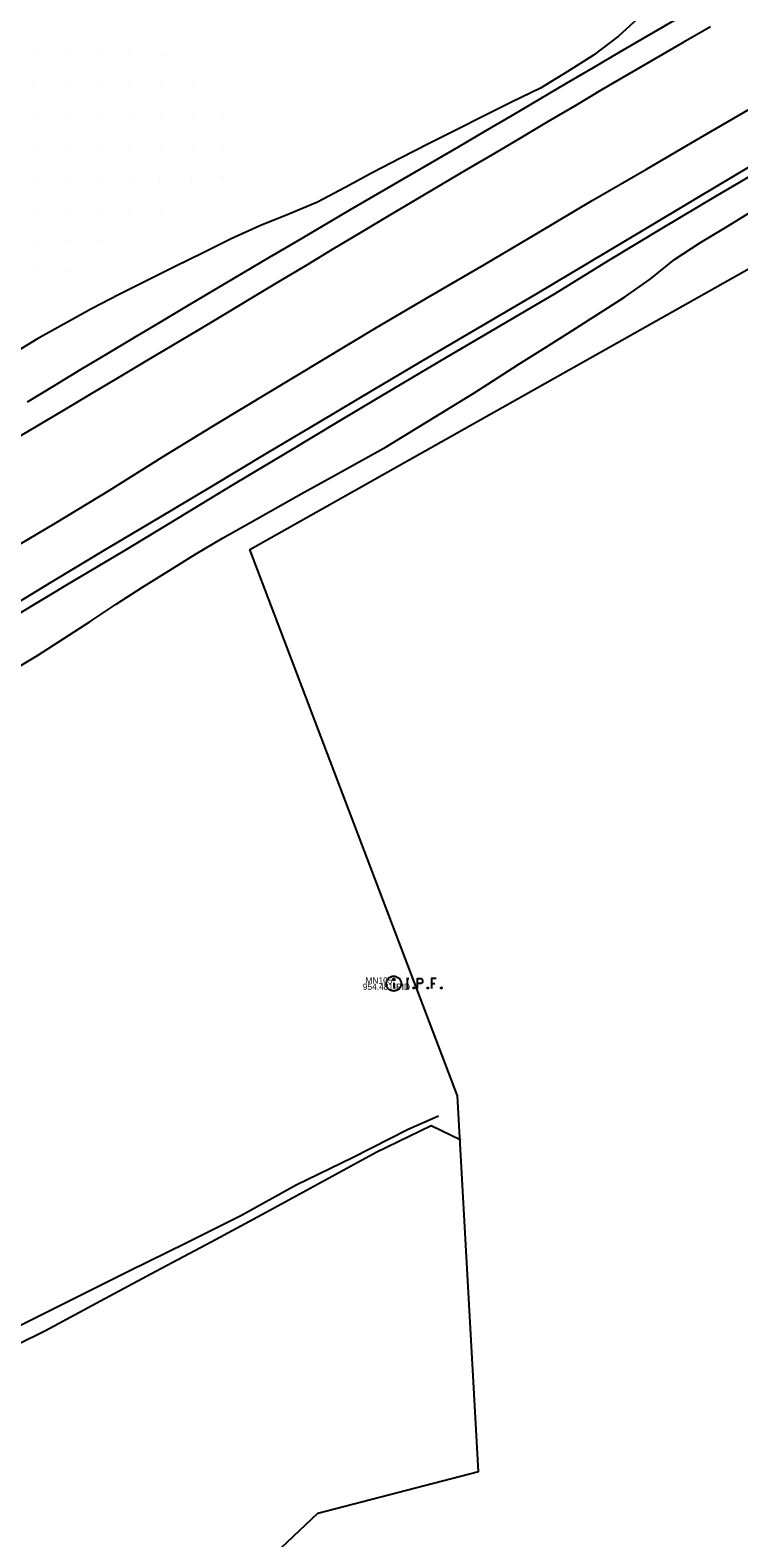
# Model space of a CAD drawing. Extents: x 2262025 to 2264532, y 740981 to 742724.
# Drawn here: x 2263398.7 to 2263511.9, y 741736.1 to 741976.8 of the extents above; entities that cross this region are included whole.
import ezdxf

# ---------------------------------------------------------------- set-up
doc = ezdxf.new("R2010")
doc.units = 0
for name, color, linetype in [('GE_X_Alignment_100_Bearings', 7, 'Continuous'), ('GE_X_Alignment_100_Cardinal_Points', 7, 'Continuous'), ('GE_X_Alignment_100_Curve_Data', 7, 'Continuous'), ('Ground Shots', 7, 'Continuous'), ('HY_X_Spring_Cells', 7, 'Continuous'), ('RS_Raster1', 7, 'Continuous'), ('RW_X_CL', 7, 'Continuous'), ('RW_X_CL_1000_Distances', 7, 'Continuous'), ('RW_X_CL_500_Curve_Data', 7, 'Continuous'), ('SV_X_Control_Cells_Found', 7, 'Continuous'), ('SV_X_Text_Comment', 7, 'Continuous'), ('SV_X_Text_Elevation', 7, 'Continuous')]:
    doc.layers.add(name, color=color, linetype=linetype)

msp = doc.modelspace()

# ---------------------------------------------------------------- linework, layer by layer
at = {"layer": 'GE_X_Alignment_100_Bearings'}
msp.add_lwpolyline([(2263396.73, 741883.54), (2263405.31, 741888.68), (2263413.89, 741893.82), (2263422.45, 741898.99), (2263431.01, 741904.16), (2263439.58, 741909.31), (2263448.16, 741914.45), (2263456.74, 741919.59), (2263465.34, 741924.68), (2263473.97, 741929.74), (2263482.6, 741934.79), (2263491.11, 741940.04), (2263499.67, 741945.22), (2263508.27, 741950.31), (2263516.88, 741955.4)], dxfattribs=at)
at = {"layer": 'GE_X_Alignment_100_Cardinal_Points'}
msp.add_lwpolyline([(2263325.57, 741733.16), (2263334.48, 741737.69), (2263343.4, 741742.23), (2263352.31, 741746.76), (2263361.22, 741751.3), (2263370.13, 741755.83), (2263378.99, 741760.47), (2263387.84, 741765.13), (2263396.69, 741769.79), (2263405.62, 741774.29), (2263414.58, 741778.74), (2263423.53, 741783.19), (2263432.48, 741787.64), (2263441.23, 741792.48), (2263450.22, 741796.85), (2263459.14, 741801.38), (2263463.94, 741803.49)], dxfattribs=at)
at = {"layer": 'GE_X_Alignment_100_Curve_Data'}
for points in [[(2263398.34, 741917.51), (2263402.62, 741920.09), (2263406.9, 741922.68), (2263411.18, 741925.26), (2263415.46, 741927.83), (2263419.75, 741930.39), (2263424.05, 741932.94), (2263428.35, 741935.48), (2263432.66, 741938.02), (2263436.96, 741940.56), (2263441.26, 741943.11), (2263445.57, 741945.64), (2263449.88, 741948.17), (2263454.2, 741950.68), (2263458.52, 741953.18), (2263462.85, 741955.69), (2263467.17, 741958.19), (2263471.48, 741960.73), (2263475.78, 741963.26), (2263480.08, 741965.81), (2263484.38, 741968.36), (2263488.7, 741970.88), (2263493.01, 741973.41), (2263497.33, 741975.92), (2263501.65, 741978.43)], [(2263513.8, 741955.1), (2263505.21, 741949.98), (2263496.62, 741944.85), (2263488.03, 741939.73), (2263479.43, 741934.64), (2263470.8, 741929.57), (2263462.18, 741924.51), (2263453.57, 741919.43), (2263444.98, 741914.3), (2263436.39, 741909.18), (2263427.81, 741904.05), (2263419.22, 741898.93), (2263410.64, 741893.8), (2263402.06, 741888.65), (2263393.5, 741883.49)]]:
    msp.add_lwpolyline(points, dxfattribs=at)
at = {"layer": 'Ground Shots'}
for p, q in [((2263399.7, 741972.96), (2263399.7, 741972.96)), ((2263404.64, 741973.02), (2263404.64, 741973.02)), ((2263409.79, 741973.1), (2263409.79, 741973.1)), ((2263414.61, 741973.12), (2263414.61, 741973.12)), ((2263419.87, 741972.97), (2263419.87, 741972.97)), ((2263399.3, 741967.95), (2263399.3, 741967.95)), ((2263404.6, 741968.07), (2263404.6, 741968.07)), ((2263409.73, 741967.98), (2263409.73, 741967.98)), ((2263414.64, 741967.99), (2263414.64, 741967.99)), ((2263419.75, 741967.96), (2263419.75, 741967.96)), ((2263424.74, 741968.08), (2263424.74, 741968.08)), ((2263399.79, 741963.01), (2263399.79, 741963.01)), ((2263404.68, 741962.95), (2263404.68, 741962.95)), ((2263409.69, 741963.03), (2263409.69, 741963.03)), ((2263414.71, 741963.04), (2263414.71, 741963.04)), ((2263419.71, 741963.3), (2263419.71, 741963.3)), ((2263424.65, 741963.03), (2263424.65, 741963.03)), ((2263429.45, 741962.82), (2263429.45, 741962.82)), ((2263399.56, 741958.03), (2263399.56, 741958.03)), ((2263404.5, 741958.25), (2263404.5, 741958.25)), ((2263409.66, 741958.06), (2263409.66, 741958.06)), ((2263414.67, 741958.06), (2263414.67, 741958.06)), ((2263419.51, 741958.1), (2263419.51, 741958.1)), ((2263424.69, 741957.97), (2263424.69, 741957.97)), ((2263429.66, 741957.98), (2263429.66, 741957.98)), ((2263419.4, 741953.21), (2263419.4, 741953.21)), ((2263424.58, 741953.14), (2263424.58, 741953.14)), ((2263429.68, 741953.28), (2263429.68, 741953.28)), ((2263399.71, 741953.05), (2263399.71, 741953.05)), ((2263404.79, 741953.07), (2263404.79, 741953.07)), ((2263409.69, 741952.95), (2263409.69, 741952.95)), ((2263414.7, 741952.97), (2263414.7, 741952.97)), ((2263399.65, 741947.97), (2263399.65, 741947.97)), ((2263404.68, 741947.98), (2263404.68, 741947.98)), ((2263409.74, 741948.11), (2263409.74, 741948.11)), ((2263414.68, 741948.08), (2263414.68, 741948.08)), ((2263419.69, 741947.93), (2263419.69, 741947.93)), ((2263399.65, 741943.04), (2263399.65, 741943.04)), ((2263404.52, 741943.21), (2263404.52, 741943.21)), ((2263409.66, 741943.08), (2263409.66, 741943.08)), ((2263399.61, 741938.22), (2263399.61, 741938.22)), ((2263404.56, 741938.22), (2263404.56, 741938.22))]:
    msp.add_line(p, q, dxfattribs=at)
at = {"layer": 'RS_Raster1'}
msp.add_lwpolyline([(2262680.86, 741714.81), (2262661.07, 741645.79), (2262765.42, 741624.79), (2262779.22, 741624.19), (2262826.51, 741606.02), (2262832.34, 741584.41), (2262933.09, 741544.98), (2262975.25, 741475.03), (2263024.25, 741455.82), (2263090.74, 741384.5), (2263137.01, 741437.31), (2263272.72, 741623.51), (2263304.66, 741651.89), (2263427.06, 741723.41), (2263444.69, 741740.07), (2263470.34, 741746.73), (2263467.01, 741806.69), (2263433.84, 741893.93), (2263732.51, 742061.95)], dxfattribs=at)
at = {"layer": 'RW_X_CL_1000_Distances'}
for points in [[(2263507.39, 741977.35), (2263503.06, 741974.86), (2263498.72, 741972.37), (2263494.41, 741969.85), (2263490.09, 741967.33), (2263485.8, 741964.77), (2263481.5, 741962.22), (2263477.19, 741959.68), (2263472.88, 741957.15), (2263468.58, 741954.62), (2263464.27, 741952.08), (2263459.98, 741949.52), (2263455.68, 741946.97), (2263451.39, 741944.41), (2263447.1, 741941.85), (2263442.81, 741939.28), (2263438.53, 741936.71), (2263434.24, 741934.13), (2263429.96, 741931.56), (2263425.66, 741929), (2263421.37, 741926.44), (2263417.08, 741923.89), (2263412.78, 741921.33), (2263408.49, 741918.77), (2263404.2, 741916.21), (2263399.91, 741913.65), (2263395.62, 741911.08)], [(2263394.24, 741893.05), (2263402.82, 741898.18), (2263411.38, 741903.33), (2263419.85, 741908.64), (2263428.36, 741913.88), (2263436.94, 741919.01), (2263445.5, 741924.17), (2263454.06, 741929.33), (2263462.68, 741934.39), (2263471.31, 741939.44), (2263479.91, 741944.53), (2263488.52, 741949.61), (2263497.16, 741954.65), (2263505.8, 741959.67), (2263514.44, 741964.69)]]:
    msp.add_lwpolyline(points, dxfattribs=at)
at = {"layer": 'RW_X_CL_500_Curve_Data'}
msp.add_lwpolyline([(2263330.2, 741733.44), (2263339.02, 741738.04), (2263347.88, 741742.61), (2263356.45, 741746.9), (2263365.31, 741751.52), (2263374.29, 741755.93), (2263383.25, 741760.36), (2263392.21, 741764.8), (2263401.18, 741769.23), (2263409.98, 741773.97), (2263418.79, 741778.71), (2263427.63, 741783.39), (2263436.43, 741788.14), (2263445.22, 741792.9), (2263454, 741797.68), (2263462.79, 741801.94), (2263467.51, 741799.66)], dxfattribs=at)
at = {"layer": 'SV_X_Control_Cells_Found'}
for points in [[(2263496.4, 741979.22), (2263492.71, 741975.87), (2263488.72, 741972.85), (2263484.51, 741970.17), (2263480.23, 741967.59), (2263475.75, 741965.38), (2263471.27, 741963.16), (2263466.81, 741960.92), (2263462.35, 741958.67), (2263457.89, 741956.41), (2263453.46, 741954.08), (2263449.07, 741951.71), (2263444.66, 741949.36), (2263440.05, 741947.44), (2263435.42, 741945.58), (2263430.87, 741943.51), (2263426.39, 741941.3), (2263421.91, 741939.09), (2263417.43, 741936.88), (2263412.98, 741934.6), (2263408.54, 741932.31), (2263399.8, 741927.47), (2263395.53, 741924.87)], [(2263391.36, 741871.88), (2263399.93, 741876.97), (2263408.3, 741882.43), (2263412.47, 741885.18), (2263416.67, 741887.89), (2263420.91, 741890.53), (2263425.17, 741893.15), (2263429.45, 741895.71), (2263433.8, 741898.18), (2263442.51, 741903.09), (2263446.89, 741905.48), (2263455.62, 741910.3), (2263469.58, 741918.88), (2263472.59, 741920.8), (2263476.81, 741923.48), (2263481.03, 741926.17), (2263485.24, 741928.85), (2263493.68, 741934.22), (2263497.78, 741937.06), (2263501.63, 741940.21), (2263505.83, 741942.9), (2263510.04, 741945.49), (2263514.35, 741948.12)]]:
    msp.add_lwpolyline(points, dxfattribs=at)
at = {"layer": 'SV_X_Text_Elevation'}
msp.add_line((2263456.81, 741824.73), (2263456.81, 741823.84), dxfattribs=at)
for points in [[(2263458.84, 741825.41), (2263459.2, 741825.41)], [(2263458.84, 741823.81), (2263459.2, 741823.81)], [(2263459.02, 741823.81), (2263459.02, 741825.41)], [(2263459.98, 741824.02), (2263460.03, 741824.02), (2263460.07, 741824), (2263460.1, 741823.95), (2263460.1, 741823.88), (2263460.07, 741823.83), (2263460.03, 741823.81), (2263459.98, 741823.81), (2263459.95, 741823.83), (2263459.91, 741823.88), (2263459.91, 741823.95), (2263459.95, 741824), (2263459.98, 741824.02)], [(2263460.58, 741823.81), (2263460.58, 741825.41), (2263461.11, 741825.41), (2263461.17, 741825.4), (2263461.25, 741825.37), (2263461.28, 741825.35), (2263461.31, 741825.32), (2263461.36, 741825.26), (2263461.39, 741825.19), (2263461.41, 741825.09), (2263461.41, 741824.94), (2263461.4, 741824.89), (2263461.38, 741824.82), (2263461.33, 741824.73), (2263461.29, 741824.69), (2263461.26, 741824.67), (2263461.2, 741824.64), (2263461.11, 741824.63), (2263460.58, 741824.63)], [(2263462.23, 741824.02), (2263462.28, 741824.02), (2263462.32, 741824), (2263462.35, 741823.95), (2263462.35, 741823.88), (2263462.32, 741823.83), (2263462.28, 741823.81), (2263462.23, 741823.81), (2263462.19, 741823.83), (2263462.16, 741823.88), (2263462.16, 741823.95), (2263462.19, 741824), (2263462.23, 741824.02)], [(2263463.59, 741825.41), (2263462.83, 741825.41), (2263462.83, 741823.81)], [(2263462.83, 741824.63), (2263463.37, 741824.63)], [(2263464.38, 741824.02), (2263464.43, 741824.02), (2263464.47, 741824), (2263464.5, 741823.95), (2263464.5, 741823.88), (2263464.47, 741823.83), (2263464.43, 741823.81), (2263464.38, 741823.81), (2263464.34, 741823.83), (2263464.31, 741823.88), (2263464.31, 741823.95), (2263464.34, 741824), (2263464.38, 741824.02)]]:
    msp.add_lwpolyline(points, dxfattribs=at)
for centre, radius in [((2263456.81, 741824.61), 1.2), ((2263456.81, 741825.26), 0.16)]:
    msp.add_circle(centre, radius, dxfattribs=at)

# ---------------------------------------------------------------- texts
at = {"layer": 'HY_X_Spring_Cells'}
msp.add_text('954.481', height=1, dxfattribs=at).set_placement((2263451.87, 741823.61))
at = {"layer": 'RW_X_CL'}
msp.add_text('IPID', height=1, dxfattribs=at).set_placement((2263456.81, 741823.61))
at = {"layer": 'SV_X_Text_Comment'}
msp.add_text('MN105', height=1, dxfattribs=at).set_placement((2263452.29, 741824.61))

doc.saveas('drawing.dxf')
